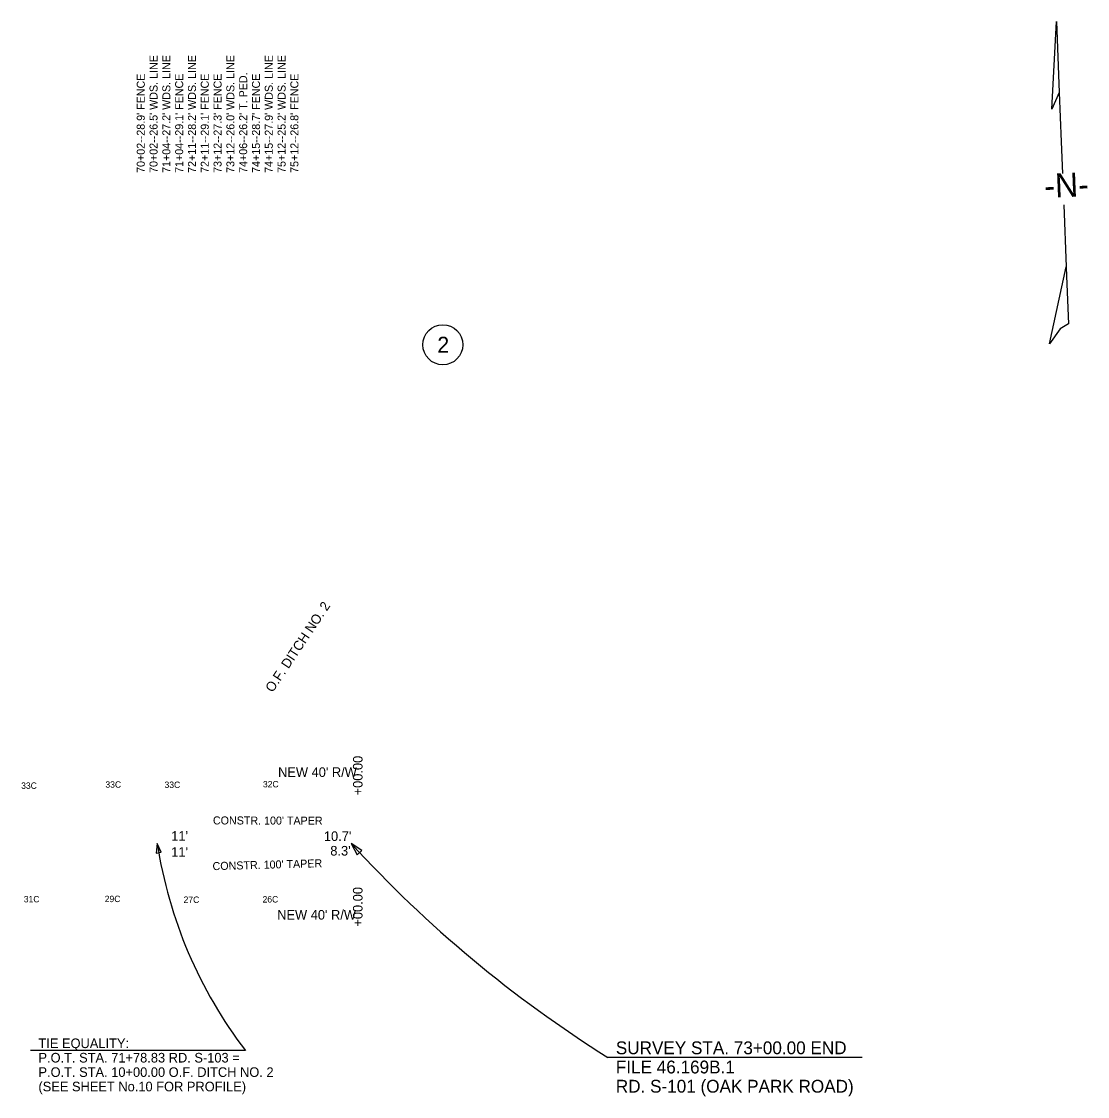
# Model space of a CAD drawing. Extents: x 1964853 to 1967410, y 1117103 to 1120421.
# Drawn here: x 1965938 to 1966604, y 1119741 to 1120412 of the extents above; entities that cross this region are included whole.
import ezdxf

# ---------------------------------------------------------------- set-up
doc = ezdxf.new("R2010")
doc.units = 0
for name, color, linetype in [('Level 12', 7, 'Continuous'), ('Level 18', 7, 'Continuous'), ('Level 2', 7, 'Continuous'), ('Level 21', 7, 'Continuous'), ('Level 23', 7, 'Continuous'), ('Level 24', 7, 'Continuous'), ('Level 33', 7, 'Continuous'), ('Level 40', 7, 'Continuous')]:
    doc.layers.add(name, color=color, linetype=linetype)

msp = doc.modelspace()

# ---------------------------------------------------------------- linework, layer by layer
at = {"layer": 'Level 12'}
msp.add_circle((1966200.79, 1120210.1), 12.5, dxfattribs=at)
at = {"layer": 'Level 2'}
for p, q in [((1966581.36, 1120357.25), (1966584.19, 1120412)), ((1966584.19, 1120412), (1966585.95, 1120367.58)), ((1966585.95, 1120367.58), (1966581.36, 1120357.25)), ((1966585.95, 1120367.58), (1966587.17, 1120336.78)), ((1966587.17, 1120336.78), (1966587.95, 1120317.15)), ((1966588.73, 1120297.55), (1966590.27, 1120258.73)), ((1966579.8, 1120210.67), (1966590.27, 1120258.73)), ((1966590.27, 1120258.73), (1966590.51, 1120252.85)), ((1966590.51, 1120252.85), (1966591.69, 1120223.1))]:
    msp.add_line(p, q, dxfattribs=at)
msp.add_lwpolyline([(1966591.69, 1120223.1), (1966586.49, 1120219.99), (1966579.8, 1120210.67)], dxfattribs=at)
at = {"layer": 'Level 21'}
for p, q in [((1966077.46, 1119769.31), (1965943.12, 1119769.31)), ((1966462.91, 1119764.99), (1966303.89, 1119764.99))]:
    msp.add_line(p, q, dxfattribs=at)
for points in [[(1966024.77, 1119893.08), (1966022.35, 1119898.58), (1966021.7, 1119892.61)], [(1966150.28, 1119894.28), (1966143.53, 1119898.58), (1966147.23, 1119891.48)]]:
    msp.add_lwpolyline(points, close=True, dxfattribs=at)
for centre, radius, start, end in [((1966302.1, 1119941.45), 283.01, 188.7129, 217.46353), ((1966720.25, 1120427.81), 782.75, 222.54163, 237.86488)]:
    msp.add_arc(centre, radius, start, end, dxfattribs=at)

# ---------------------------------------------------------------- texts
at = {"layer": 'Level 12'}
msp.add_text('2', height=10, dxfattribs=at).set_placement((1966197.32, 1120205.1))
at = {"layer": 'Level 18'}
for s, p in [('33C', (1965937.32, 1119932.74)), ('33C', (1965989.96, 1119933.43)), ('33C', (1966026.9, 1119933.28)), ('32C', (1966088.41, 1119933.65)), ('31C', (1965938.97, 1119861.85)), ('29C', (1965989.55, 1119861.99)), ('27C', (1966038.82, 1119861.49)), ('26C', (1966088.14, 1119861.74))]:
    msp.add_text(s, height=4, rotation=360, dxfattribs=at).set_placement(p)
at = {"layer": 'Level 2'}
msp.add_text('-N-', height=15, rotation=2.27337, dxfattribs=at).set_placement((1966576.88, 1120301.79))
at = {"layer": 'Level 21'}
for s, height, p in [('TIE EQUALITY:', 6, (1965948.12, 1119770.81)), ('SURVEY STA. 73+00.00 END', 8, (1966308.89, 1119766.99)), ('P.O.T. STA. 71+78.83 RD. S-103 =', 6, (1965948.12, 1119761.81)), ('FILE 46.169B.1', 8, (1966308.89, 1119754.99)), ('P.O.T. STA. 10+00.00 O.F. DITCH NO. 2', 6, (1965948.12, 1119752.81)), ('(SEE SHEET No.10 FOR PROFILE)', 6, (1965948.12, 1119743.81)), ('RD. S-101 (OAK PARK ROAD)', 8, (1966308.89, 1119742.99))]:
    msp.add_text(s, height=height, dxfattribs=at).set_placement(p)
at = {"layer": 'Level 23'}
msp.add_text('O.F. DITCH NO. 2', height=6, rotation=56.35061, dxfattribs=at).set_placement((1966094.45, 1119992.54))
at = {"layer": 'Level 24'}
for s, p in [("70+02--26.5' WDS. LINE", (1966022.55, 1120317.43)), ("71+04--27.2' WDS. LINE", (1966030.55, 1120317.43)), ("72+11--28.2' WDS. LINE", (1966046.55, 1120317.43)), ("73+12--26.0' WDS. LINE", (1966070.55, 1120317.43)), ("74+15--27.9' WDS. LINE", (1966094.55, 1120317.43)), ("75+12--25.2' WDS. LINE", (1966102.55, 1120317.43)), ("70+02--28.9' FENCE  ", (1966014.55, 1120317.43)), ("71+04--29.1' FENCE  ", (1966038.55, 1120317.43)), ("72+11--29.1' FENCE  ", (1966054.55, 1120317.43)), ("73+12--27.3' FENCE  ", (1966062.55, 1120317.43)), ("74+06--26.2' T. PED.  ", (1966078.55, 1120317.43)), ("74+15--28.7' FENCE  ", (1966086.55, 1120317.43)), ("75+12--26.8' FENCE  ", (1966110.55, 1120317.43))]:
    msp.add_text(s, height=5, rotation=90, dxfattribs=at).set_placement(p)
at = {"layer": 'Level 33'}
for p in [(1966150.64, 1119928.63), (1966150.64, 1119846.66)]:
    msp.add_text('+00.00', height=6, rotation=90, dxfattribs=at).set_placement(p)
for p in [(1966097.85, 1119940.16), (1966097.3, 1119851.06)]:
    msp.add_text("NEW 40' R/W", height=6, dxfattribs=at).set_placement(p)
at = {"layer": 'Level 40'}
for rotation, p in [(359.85092, (1966057.14, 1119910.52)), (1.56143, (1966056.97, 1119881.93))]:
    msp.add_text("CONSTR. 100' TAPER", height=5, rotation=rotation, dxfattribs=at).set_placement(p)
for s, p in [("11'", (1966031.08, 1119900.31)), ("10.7'", (1966126.47, 1119900.18)), ("11'", (1966031.08, 1119890.3)), ("8.3'", (1966130.48, 1119891.07))]:
    msp.add_text(s, height=6, dxfattribs=at).set_placement(p)

doc.saveas('drawing.dxf')
